// Mitsubishi GX Works2 project: 红绿灯测试(王)   PLC: FX3U/FX3UC

PROGRAM MAIN
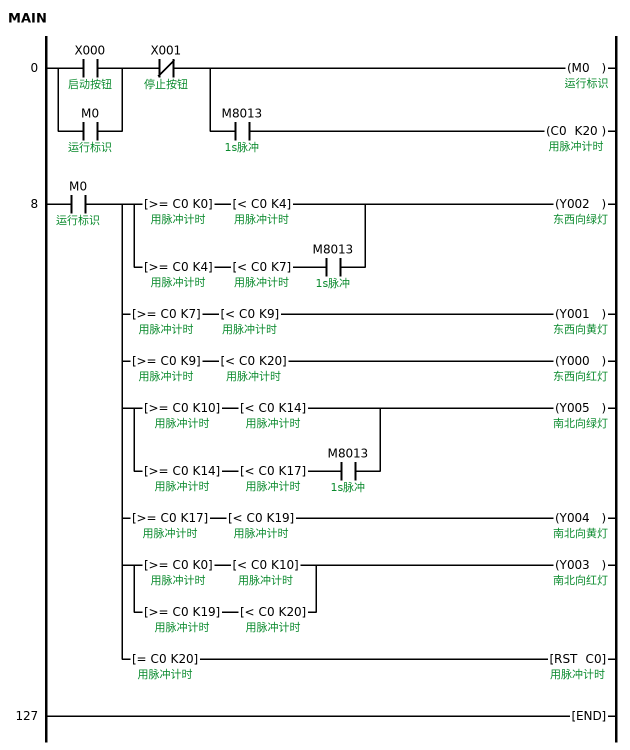
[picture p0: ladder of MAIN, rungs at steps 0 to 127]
0     LD      X000  ; 启动按钮
      OR      M0  ; 运行标识
      ANI     X001  ; 停止按钮
      OUT     M0  ; 运行标识
      AND     M8013  ; 1s脉冲
      OUT     C0 K20  ; 用脉冲计时
8     LD      M0  ; 运行标识
      MPS
      LD>=    C0 K0  ; 用脉冲计时
      AND<    C0 K4  ; 用脉冲计时
      LD>=    C0 K4  ; 用脉冲计时
      AND<    C0 K7  ; 用脉冲计时
      AND     M8013  ; 1s脉冲
      ORB
      ANB
      OUT     Y002  ; 东西向绿灯
        [note] 0-4秒东西向绿灯,4-7秒闪烁
      MRD
      AND>=   C0 K7  ; 用脉冲计时
      AND<    C0 K9  ; 用脉冲计时
      OUT     Y001  ; 东西向黄灯
        [note] 7-9秒东西向黄灯
      MRD
      AND>=   C0 K9  ; 用脉冲计时
      AND<    C0 K20  ; 用脉冲计时
      OUT     Y000  ; 东西向红灯
        [note] 9-20秒东西向红灯
      MRD
      LD>=    C0 K10  ; 用脉冲计时
      AND<    C0 K14  ; 用脉冲计时
      LD>=    C0 K14  ; 用脉冲计时
      AND<    C0 K17  ; 用脉冲计时
      AND     M8013  ; 1s脉冲
      ORB
      ANB
      OUT     Y005  ; 南北向绿灯
        [note] 10-14秒南北向绿灯,14-17秒闪烁
      MRD
      AND>=   C0 K17  ; 用脉冲计时
      AND<    C0 K19  ; 用脉冲计时
      OUT     Y004  ; 南北向黄灯
        [note] 17-19秒南北向黄灯
      MRD
      LD>=    C0 K0  ; 用脉冲计时
      AND<    C0 K10  ; 用脉冲计时
      LD>=    C0 K19  ; 用脉冲计时
      AND<    C0 K20  ; 用脉冲计时
      ORB
      ANB
      OUT     Y003  ; 南北向红灯
        [note] 0-10秒和19-20秒南北向红灯
      MPP
      AND=    C0 K20  ; 用脉冲计时
      RST     C0  ; 用脉冲计时
        [note] 20秒重置计数器
127   END
END_PROGRAM
